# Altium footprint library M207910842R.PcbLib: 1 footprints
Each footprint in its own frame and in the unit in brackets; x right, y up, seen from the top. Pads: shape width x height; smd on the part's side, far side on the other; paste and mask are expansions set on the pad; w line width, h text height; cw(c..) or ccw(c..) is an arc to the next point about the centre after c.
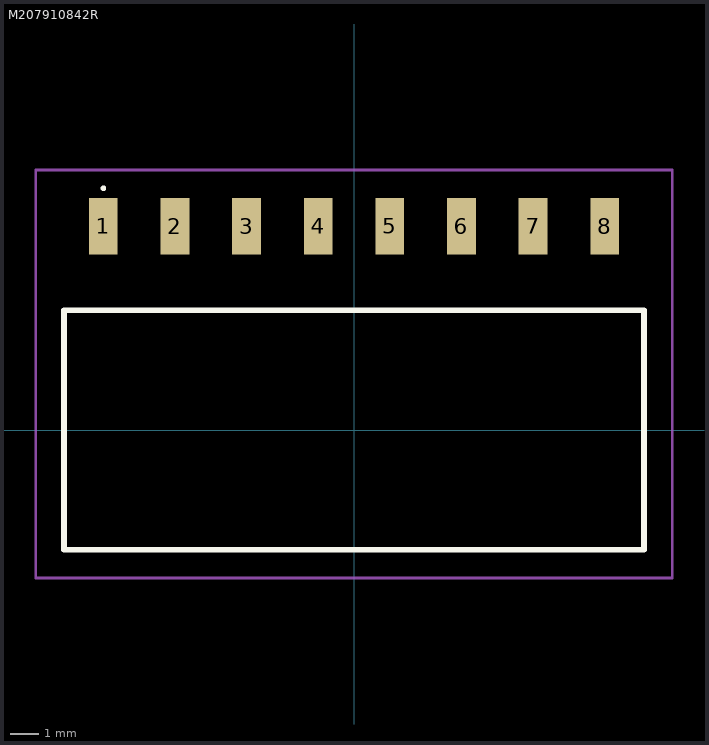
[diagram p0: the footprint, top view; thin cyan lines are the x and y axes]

## M207910842R [mm]
pads (8):
  rect 1.02x2 smd: 1(-8.89,7.224) 2(-6.35,7.224) 3(-3.81,7.224) 4(-1.27,7.224) 5(1.27,7.224) 6(3.81,7.224) 7(6.35,7.224) 8(8.89,7.224)
Top Overlay:
  lines w0.1: -8.89,8.524 -8.89,8.524 ; -8.89,8.524 ccw(c-8.89,8.574) -8.89,8.624 ; -8.89,8.524 cw(c-8.89,8.574) -8.89,8.624 ; -8.89,8.625 -8.89,8.625
  lines w0.2: -10.285,-4.25 -10.285,4.25 10.285,4.25 10.285,-4.25 -10.285,-4.25
Mechanical 15:
  lines w0.1: -10.285,-4.25 10.285,-4.25 10.285,4.25 -10.285,4.25 -10.285,-4.25
Mechanical 20:
  lines w0.1: -11.285,-5.25 11.285,-5.25 11.285,9.224 -11.285,9.224 -11.285,-5.25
